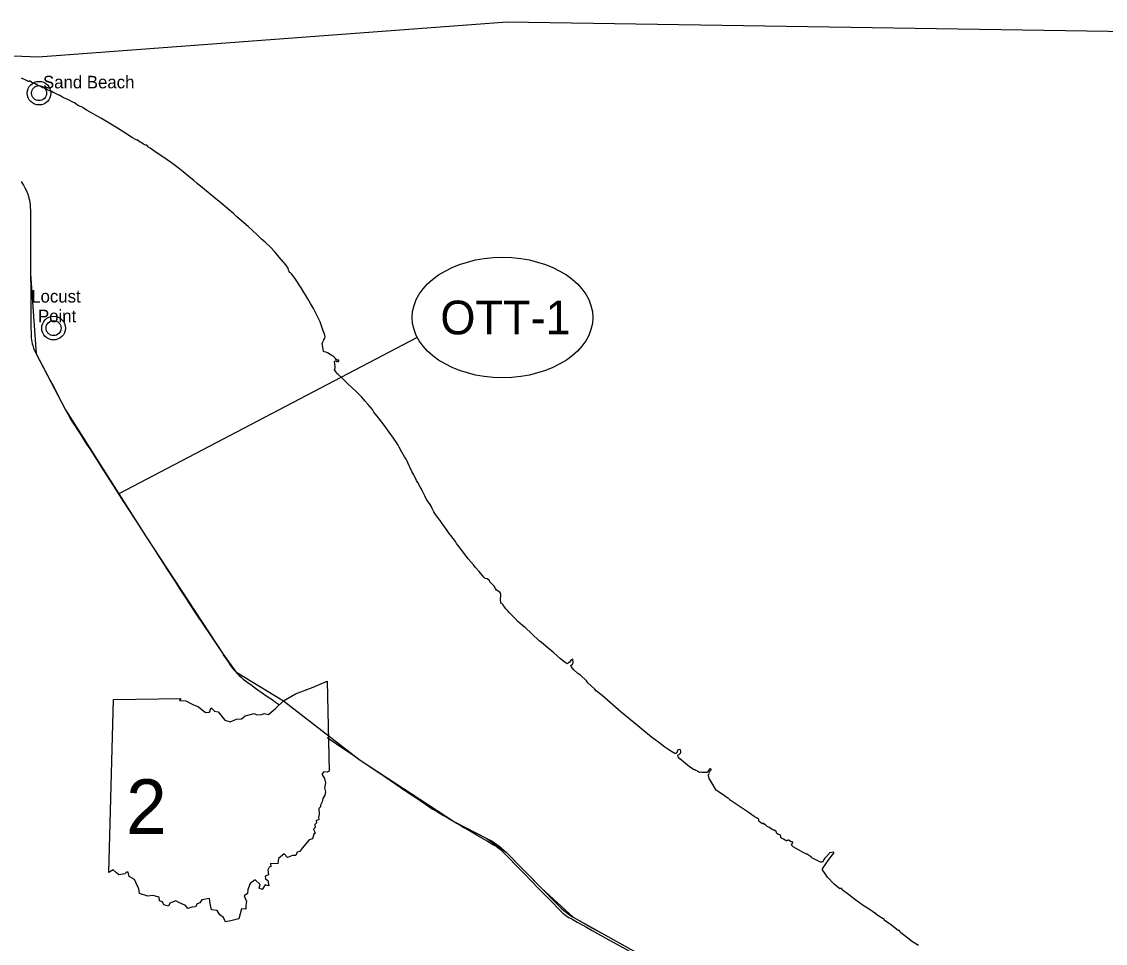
# Model space of a CAD drawing. Extents: x -82 to 873, y 0 to 440.
# Drawn here: x 310.6 to 400.6, y 192.1 to 268.6 of the extents above; entities that cross this region are included whole.
import ezdxf

# ---------------------------------------------------------------- set-up
doc = ezdxf.new("R2010")
doc.units = 0
for name, color, linetype in [('DV_X_Corp_Line', 7, 'Continuous'), ('DV_X_County_Line', 7, 'Continuous'), ('GM_P_US_Alignment', 7, 'Continuous'), ('GM_X_County', 7, 'Continuous'), ('GM_X_Interstate_Route', 7, 'Continuous'), ('PV_P_Text', 7, 'Continuous'), ('SH_Data', 7, 'Continuous')]:
    doc.layers.add(name, color=color, linetype=linetype)

msp = doc.modelspace()

# ---------------------------------------------------------------- linework, layer by layer
at = {"layer": 'DV_X_Corp_Line'}
for centre, radius in [((312.035, 262.713), 0.982), ((312.035, 262.713), 0.623), ((313.239, 243.203), 0.982), ((313.239, 243.203), 0.623)]:
    msp.add_circle(centre, radius, dxfattribs=at)
at = {"layer": 'DV_X_County_Line'}
for p, q in [((311.973, 265.73), (350.916, 268.65)), ((350.916, 268.65), (423.261, 267.513)), ((282.754, 267.019), (311.973, 265.73))]:
    msp.add_line(p, q, dxfattribs=at)
at = {"layer": 'GM_P_US_Alignment'}
msp.add_lwpolyline([(311.334, 247.708), (311.793, 241.068), (314.238, 236.419), (320.869, 225.952), (327.314, 216.112), (328.371, 214.651), (332.341, 212.251), (338.714, 207.336), (346.525, 202.192), (349.222, 200.826), (350.82, 199.691), (353.754, 196.704), (356.379, 194.294), (361.645, 191.348), (365.204, 189.06)], dxfattribs=at)
at = {"layer": 'GM_X_County'}
msp.add_lwpolyline([(385.067, 191.936), (384.564, 192.229), (384.181, 192.533), (383.818, 192.818), (383.564, 193.013), (383.533, 193.064), (383.51, 193.134), (383.482, 193.173), (383.436, 193.177), (383.393, 193.177), (382.721, 193.708), (382.254, 194.008), (382.241, 194.074), (382.226, 194.117), (382.187, 194.145), (382.132, 194.145), (381.781, 194.371), (381.57, 194.519), (381.535, 194.578), (381.496, 194.609), (381.445, 194.613), (381.238, 194.757), (381.043, 194.905), (380.477, 195.261), (379.865, 195.709), (379.256, 196.154), (378.725, 196.552), (378.702, 196.661), (378.643, 196.7), (378.542, 196.646), (378.077, 197.032), (377.515, 197.606), (377.34, 197.848), (377.086, 198.214), (377.103, 198.29), (377.375, 198.712), (377.572, 198.989), (377.825, 199.319), (378.036, 199.613), (378.04, 199.693), (377.691, 199.615), (377.638, 199.565), (377.431, 199.332), (377.281, 199.188), (377.248, 199.096), (377.084, 198.856), (376.941, 198.86), (376.495, 199.062), (376.163, 199.25), (376.174, 199.278), (375.78, 199.538), (375.755, 199.523), (375.535, 199.636), (374.656, 200.133), (374.594, 200.18), (374.547, 200.231), (374.525, 200.287), (374.585, 200.365), (374.619, 200.428), (374.644, 200.465), (374.626, 200.51), (374.578, 200.55), (374.549, 200.543), (374.515, 200.529), (374.481, 200.535), (374.286, 200.667), (374.232, 200.671), (374.204, 200.643), (374.172, 200.64), (374.126, 200.598), (373.851, 200.761), (373.648, 200.877), (373.643, 201.014), (373.617, 201.075), (373.516, 201.116), (373.435, 201.136), (373.292, 201.238), (373.287, 201.324), (373.252, 201.39), (373.171, 201.441), (373.155, 201.491), (373.135, 201.522), (373.018, 201.522), (372.917, 201.552), (372.653, 201.76), (372.511, 201.826), (372.379, 201.928), (372.257, 202.009), (372.191, 202.09), (372.115, 202.07), (372.085, 202.049), (371.811, 202.257), (371.816, 202.389), (371.679, 202.496), (371.588, 202.521), (371.42, 202.653), (370.913, 203.013), (369.517, 203.952), (369.441, 204.014), (369.345, 204.081), (369.306, 204.144), (369.239, 204.158), (368.956, 204.35), (368.442, 204.715), (368.274, 204.84), (367.914, 205.43), (367.698, 205.79), (367.626, 206.039), (367.631, 206.121), (367.684, 206.174), (367.708, 206.246), (367.698, 206.299), (367.698, 206.332), (367.713, 206.39), (367.761, 206.428), (367.809, 206.462), (367.838, 206.515), (367.842, 206.567), (367.804, 206.615), (367.742, 206.615), (367.689, 206.553), (367.617, 206.419), (367.487, 206.294), (367.391, 206.289), (367.113, 206.289), (367.012, 206.313), (366.897, 206.303), (366.81, 206.342), (366.714, 206.404), (366.566, 206.476), (366.489, 206.51), (366.431, 206.514), (366.052, 206.769), (365.707, 207.033), (365.241, 207.421), (365.121, 207.609), (365.087, 207.705), (365.121, 207.777), (365.203, 207.805), (365.303, 207.897), (365.337, 207.978), (365.337, 208.079), (365.294, 208.17), (365.217, 208.204), (365.111, 208.18), (365.054, 208.112), (365.03, 208.055), (364.996, 207.92), (364.929, 207.868), (364.847, 207.872), (364.507, 208.06), (363.998, 208.4), (363.504, 208.799), (362.904, 209.23), (362.256, 209.758), (361.766, 210.161), (360.374, 211.308), (359.712, 211.884), (358.795, 212.69), (358.339, 213.055), (358.171, 213.252), (357.619, 213.736), (357.504, 213.905), (357, 214.37), (356.77, 214.533), (356.448, 214.831), (356.223, 215.095), (356.21, 215.171), (356.323, 215.306), (356.381, 215.397), (356.371, 215.709), (356.174, 215.56), (356.088, 215.473), (355.987, 215.378), (355.882, 215.315), (355.738, 215.421), (355.339, 215.747), (354.783, 216.222), (354.159, 216.769), (353.746, 217.115), (353.583, 217.206), (352.93, 217.835), (352.416, 218.343), (352.176, 218.516), (351.807, 218.847), (351.581, 219.087), (351.087, 219.586), (350.948, 219.745), (350.799, 219.903), (350.655, 220.076), (350.578, 220.177), (350.564, 220.215), (350.453, 220.325), (350.396, 220.369), (350.367, 220.68), (350.381, 220.978), (350.376, 221.103), (350.343, 221.204), (350.29, 221.28), (350.036, 221.444), (349.954, 221.588), (349.834, 221.76), (349.58, 222.01), (349.479, 222.13), (349.441, 222.242), (349.239, 222.394), (349.085, 222.418), (348.961, 222.518), (348.586, 222.979), (348.265, 223.344), (348.116, 223.536), (347.684, 224.049), (347.295, 224.572), (346.81, 225.182), (346.705, 225.302), (346.613, 225.475), (346.239, 225.988), (346.1, 226.142), (345.97, 226.314), (345.745, 226.665), (345.524, 226.982), (345.341, 227.236), (345.217, 227.404), (345.125, 227.5), (344.914, 227.797), (344.828, 227.941), (344.689, 228.229), (344.593, 228.412), (344.501, 228.541), (344.305, 228.853), (344.156, 229.093), (344.06, 229.271), (343.954, 229.496), (343.867, 229.664), (343.724, 229.976), (343.484, 230.384), (343.383, 230.538), (343.215, 230.907), (343.172, 231.017), (342.999, 231.301), (342.836, 231.656), (342.769, 231.766), (342.682, 231.963), (342.61, 232.15), (342.523, 232.313), (342.397, 232.505), (342.167, 232.893), (341.942, 233.304), (341.871, 233.474), (341.652, 233.78), (341.334, 234.257), (341.104, 234.563), (340.704, 235.138), (340.223, 235.762), (339.845, 236.233), (339.713, 236.431), (339.522, 236.666), (339.346, 236.89), (339.089, 237.159), (338.832, 237.465), (338.7, 237.608), (338.35, 237.958), (338.059, 238.226), (337.605, 238.665), (337.145, 239.092), (336.887, 239.338), (336.772, 239.431), (336.718, 239.552), (336.574, 239.729), (336.592, 239.816), (336.626, 239.872), (336.635, 239.954), (336.592, 240.263), (336.561, 240.38), (336.574, 240.423), (336.596, 240.449), (336.657, 240.48), (336.696, 240.48), (336.731, 240.441), (336.787, 240.441), (336.835, 240.454), (336.869, 240.436), (336.915, 240.428), (336.943, 240.48), (336.939, 240.514), (336.917, 240.534), (336.878, 240.53), (336.826, 240.536), (336.778, 240.549), (336.722, 240.592), (336.644, 240.684), (336.513, 240.809), (336.353, 240.914), (336.132, 241.061), (335.984, 241.157), (335.862, 241.204), (335.737, 241.235), (335.654, 241.252), (335.541, 241.951), (335.611, 241.994), (335.637, 242.107), (335.691, 242.226), (335.762, 242.359), (335.784, 242.485), (335.767, 242.615), (335.741, 242.702), (335.624, 242.966), (335.532, 243.214), (335.367, 243.722), (335.268, 243.943), (334.959, 244.542), (334.829, 244.824), (334.59, 245.249), (334.36, 245.623), (333.792, 246.543), (333.336, 247.276), (333.206, 247.463), (333.002, 247.719), (332.923, 247.797), (332.867, 247.814), (332.802, 247.892), (332.754, 248.005), (332.715, 248.188), (332.533, 248.444), (331.986, 249.086), (331.756, 249.364), (331.587, 249.572), (331.257, 249.915), (330.862, 250.297), (330.679, 250.44), (330.51, 250.575), (330.397, 250.687), (330.111, 250.974), (329.39, 251.629), (328.461, 252.454), (328.175, 252.718), (327.71, 253.118), (327.285, 253.478), (327.124, 253.604), (326.56, 254.068), (325.77, 254.719), (325.162, 255.218), (324.889, 255.457), (324.511, 255.756), (323.995, 256.19), (323.587, 256.507), (323.153, 256.833), (322.493, 257.325), (321.838, 257.733), (321.252, 258.132), (321.074, 258.254), (321.056, 258.31), (320.922, 258.393), (320.869, 258.382), (320.712, 258.484), (320.26, 258.751), (320.271, 258.796), (320.195, 258.84), (320.149, 258.809), (319.732, 259.039), (319.377, 259.293), (318.547, 259.799), (317.208, 260.621), (316.041, 261.276), (315.724, 261.474), (315.635, 261.558), (315.459, 261.608), (315.231, 261.726), (315.082, 261.821), (314.988, 261.901), (314.884, 261.927), (314.466, 262.146), (314.083, 262.325), (313.968, 262.376), (313.853, 262.45), (313.76, 262.526), (313.736, 262.541), (313.684, 262.55), (313.499, 262.641), (313.335, 262.726), (313.289, 262.739), (313.213, 262.767), (313.083, 262.841), (312.994, 262.869), (312.9, 262.895), (312.762, 262.956), (312.673, 263.017), (312.614, 263.056), (312.534, 263.09), (312.473, 263.14), (312.351, 263.164), (312.147, 263.255), (311.954, 263.342), (311.861, 263.407), (311.867, 263.457), (311.8, 263.442), (311.644, 263.505), (311.514, 263.574), (311.427, 263.596), (311.399, 263.644), (311.34, 263.661), (311.249, 263.724), (311.21, 263.715), (311.175, 263.693), (311.132, 263.693), (311.097, 263.698), (310.871, 263.819), (310.761, 263.874), (310.676, 263.91), (310.62, 263.939), (310.572, 263.947)], dxfattribs=at)
at = {"layer": 'GM_X_Interstate_Route'}
for points in [[(310.542, 255.38), (310.634, 255.244), (310.742, 255.07), (310.859, 254.863), (310.961, 254.648), (311.014, 254.52), (311.061, 254.408), (311.147, 254.145), (311.191, 253.989), (311.227, 253.831), (311.263, 253.63), (311.29, 253.429), (311.309, 253.226), (311.318, 253.023), (311.324, 252.697), (311.321, 252.002), (311.32, 251.664), (311.318, 251.082)], [(311.318, 251.082), (311.316, 250.463), (311.318, 250.169), (311.321, 249.668), (311.334, 247.708), (311.343, 246.388), (311.348, 245.68), (311.353, 245.023), (311.354, 244.572), (311.363, 243.633), (311.363, 243.599), (311.365, 243.138), (311.367, 242.858), (311.375, 242.561), (311.384, 242.396), (311.402, 242.233), (311.427, 242.07), (311.462, 241.909), (311.506, 241.75), (311.538, 241.648), (311.58, 241.528), (311.612, 241.447), (311.627, 241.413), (311.683, 241.289), (311.793, 241.068), (312.538, 239.652), (312.643, 239.451), (312.9, 238.961), (313.112, 238.563), (313.934, 237.001), (314.238, 236.419), (314.449, 236.021), (314.608, 235.733), (314.656, 235.653), (314.755, 235.486), (315.441, 234.414), (315.984, 233.57), (316.24, 233.171), (316.771, 232.342), (317.393, 231.376), (317.935, 230.527), (318.034, 230.373), (318.197, 230.119), (319.052, 228.784), (320.449, 226.608), (320.869, 225.952), (321.609, 224.804), (321.928, 224.311), (322.513, 223.419), (322.626, 223.243), (322.846, 222.902), (323.27, 222.248), (323.785, 221.439), (324.328, 220.615), (324.415, 220.483), (324.977, 219.626), (325.84, 218.33), (326.134, 217.886), (326.791, 216.896), (327.314, 216.112)], [(327.314, 216.112), (327.337, 216.078), (327.68, 215.568), (327.936, 215.197), (328.083, 215), (328.237, 214.807), (328.371, 214.651), (328.483, 214.531), (328.653, 214.364), (328.658, 214.358), (328.81, 214.22), (328.997, 214.06), (329.19, 213.906), (329.486, 213.687), (329.609, 213.598)], [(329.609, 213.598), (330.018, 213.303), (330.674, 212.844), (331.033, 212.595), (331.299, 212.404), (331.662, 212.146), (332, 211.908)], [(335.96, 209.213), (336.137, 209.093), (336.746, 208.675), (337.187, 208.375), (338.104, 207.753), (338.714, 207.336), (340.782, 205.925), (341.664, 205.325), (342.376, 204.839), (342.79, 204.56), (343.397, 204.153), (343.968, 203.772), (344.114, 203.674), (344.444, 203.457), (344.737, 203.264), (345.124, 203.024), (345.621, 202.726), (346.001, 202.498), (346.525, 202.192), (346.713, 202.083), (347.089, 201.865), (347.37, 201.705), (347.439, 201.669)], [(347.439, 201.669), (348.192, 201.224), (348.251, 201.185), (349.282, 200.588), (349.779, 200.298), (349.99, 200.17), (350.127, 200.078), (350.258, 199.978), (350.343, 199.906), (350.384, 199.871), (350.503, 199.757), (352.198, 198.025), (353.061, 197.145), (353.357, 196.84), (353.49, 196.703), (354.009, 196.176), (354.44, 195.736), (354.67, 195.501), (355.157, 195), (355.388, 194.767), (355.536, 194.626), (355.661, 194.519), (355.757, 194.444), (355.892, 194.351), (356.03, 194.263), (356.35, 194.078), (356.709, 193.88), (357.25, 193.584), (357.501, 193.445), (357.968, 193.186), (359.116, 192.545), (362.525, 190.645)], [(347.439, 201.669), (348.622, 201.118), (349.002, 200.936), (349.222, 200.826), (349.439, 200.709), (349.651, 200.585), (349.858, 200.453), (350.061, 200.314), (350.258, 200.168), (350.403, 200.052), (350.42, 200.039), (350.451, 200.015), (350.669, 199.829), (350.82, 199.691), (351.053, 199.46), (351.915, 198.581), (352.977, 197.495), (353.381, 197.086), (353.406, 197.059), (353.754, 196.704), (355.015, 195.412), (355.218, 195.208), (355.399, 195.04), (355.616, 194.851), (355.807, 194.695), (355.971, 194.571), (356.172, 194.429), (356.379, 194.294), (356.591, 194.167), (356.983, 193.944), (357.952, 193.405), (358.776, 192.945), (361.645, 191.348)]]:
    msp.add_lwpolyline(points, dxfattribs=at)
at = {"layer": 'PV_P_Text'}
msp.add_line((317.824, 198), (318.225, 212.363), dxfattribs=at)
msp.add_line((317.824, 198), (318.225, 212.363), dxfattribs=at)
for points in [[(318.225, 212.363), (323.797, 212.457), (323.71, 212.283), (324.236, 212.247), (324.795, 211.94), (325.267, 211.746), (325.845, 211.29), (326.191, 211.295), (326.337, 211.669), (326.602, 211.38), (326.916, 211.329), (327.459, 210.641), (327.908, 210.492), (328.445, 210.728), (328.846, 210.767), (329.14, 211), (329.904, 211.199), (330.118, 211.08), (330.523, 211.104), (330.726, 211.192), (331.079, 211.113), (331.701, 211.635), (332.341, 212.251), (333.325, 212.832), (334.795, 213.383), (335.957, 213.875), (336.126, 206.422)], [(318.225, 212.363), (323.797, 212.457), (323.71, 212.283), (324.236, 212.247), (324.795, 211.94), (325.267, 211.746), (325.845, 211.29), (326.191, 211.295), (326.337, 211.669), (326.602, 211.38), (326.916, 211.329), (327.459, 210.641), (327.908, 210.492), (328.445, 210.728), (328.846, 210.767), (329.14, 211), (329.904, 211.199), (330.118, 211.08), (330.523, 211.104), (330.726, 211.192), (331.079, 211.113), (331.701, 211.635), (332.341, 212.251), (333.325, 212.832), (334.795, 213.383), (335.957, 213.875), (336.126, 206.422)], [(336.126, 206.422), (335.954, 206.317), (335.687, 206.367), (335.508, 206.157), (335.73, 205.809), (335.835, 205.44), (335.742, 205.034), (335.834, 204.699), (335.771, 204.419), (335.603, 204.14), (335.545, 203.874), (335.403, 203.593), (335.415, 203.437), (335.279, 203.312), (335.303, 202.846), (335.235, 202.588), (335.258, 202.365), (335.038, 202.306), (335.088, 202.122), (334.948, 201.98), (334.978, 201.735), (334.819, 201.579), (334.973, 201.267), (334.849, 201.167), (334.746, 200.787), (334.463, 200.71), (333.897, 200.014), (333.697, 199.751), (333.472, 199.686), (333.348, 199.416), (333.072, 199.415), (332.653, 199.228), (332.383, 199.55), (331.908, 199.162), (331.854, 198.714), (331.254, 198.728), (331.278, 198.502), (331.144, 198.436), (331.022, 198.209), (331.093, 197.806), (330.812, 197.703), (330.846, 197.469), (331.026, 197.326), (331.106, 196.879), (330.808, 196.969), (330.563, 196.592), (330.312, 196.681), (330.394, 197), (329.97, 197.384), (329.568, 197.077), (329.359, 196.585), (329.356, 196.255), (329.057, 196.055), (329.249, 195.588), (329.214, 195.266), (329.22, 194.96), (328.846, 194.971), (328.619, 194.146)], [(336.126, 206.422), (335.954, 206.317), (335.687, 206.367), (335.508, 206.157), (335.73, 205.809), (335.835, 205.44), (335.742, 205.034), (335.834, 204.699), (335.771, 204.419), (335.603, 204.14), (335.545, 203.874), (335.403, 203.593), (335.415, 203.437), (335.279, 203.312), (335.303, 202.846), (335.235, 202.588), (335.258, 202.365), (335.038, 202.306), (335.088, 202.122), (334.948, 201.98), (334.978, 201.735), (334.819, 201.579), (334.973, 201.267), (334.849, 201.167), (334.746, 200.787), (334.463, 200.71), (333.897, 200.014), (333.697, 199.751), (333.472, 199.686), (333.348, 199.416), (333.072, 199.415), (332.653, 199.228), (332.383, 199.55), (331.908, 199.162), (331.854, 198.714), (331.254, 198.728), (331.278, 198.502), (331.144, 198.436), (331.022, 198.209), (331.093, 197.806), (330.812, 197.703), (330.846, 197.469), (331.026, 197.326), (331.106, 196.879), (330.808, 196.969), (330.563, 196.592), (330.312, 196.681), (330.394, 197), (329.97, 197.384), (329.568, 197.077), (329.359, 196.585), (329.356, 196.255), (329.057, 196.055), (329.249, 195.588), (329.214, 195.266), (329.22, 194.96), (328.846, 194.971), (328.619, 194.146)], [(328.619, 194.146), (327.969, 193.989), (327.518, 193.894), (327.358, 194.269), (327.036, 194.466), (326.825, 194.844), (326.362, 194.895), (326.252, 195.413), (326.2, 195.833), (325.566, 195.729), (325.392, 195.472), (325.168, 195.403), (325.037, 195.144), (324.731, 195.123), (324.402, 195.001), (324.187, 195.254), (323.648, 195.509), (323.406, 195.641), (322.899, 195.436), (322.791, 195.195), (322.388, 195.301), (322.294, 195.571), (322.05, 195.652), (321.996, 195.938), (321.474, 196.09), (321.075, 196.03), (320.372, 196.26), (320.329, 196.636), (320.09, 197.095), (319.964, 197.413), (319.52, 197.656), (319.43, 198.035), (319.287, 198.024), (319.157, 197.87), (318.663, 197.799), (318.466, 197.954), (318.189, 198.218), (317.824, 198)], [(328.619, 194.146), (327.969, 193.989), (327.518, 193.894), (327.358, 194.269), (327.036, 194.466), (326.825, 194.844), (326.362, 194.895), (326.252, 195.413), (326.2, 195.833), (325.566, 195.729), (325.392, 195.472), (325.168, 195.403), (325.037, 195.144), (324.731, 195.123), (324.402, 195.001), (324.187, 195.254), (323.648, 195.509), (323.406, 195.641), (322.899, 195.436), (322.791, 195.195), (322.388, 195.301), (322.294, 195.571), (322.05, 195.652), (321.996, 195.938), (321.474, 196.09), (321.075, 196.03), (320.372, 196.26), (320.329, 196.636), (320.09, 197.095), (319.964, 197.413), (319.52, 197.656), (319.43, 198.035), (319.287, 198.024), (319.157, 197.87), (318.663, 197.799), (318.466, 197.954), (318.189, 198.218), (317.824, 198)]]:
    msp.add_lwpolyline(points, dxfattribs=at)
at = {"layer": 'SH_Data'}
msp.add_line((343.442, 242.433), (318.659, 229.439), dxfattribs=at)
msp.add_ellipse((350.522, 244.083), major_axis=(7.5, 0), ratio=0.666667, dxfattribs=at)

# ---------------------------------------------------------------- texts
at = {"layer": 'DV_X_Corp_Line'}
for s, p in [('Sand Beach', (312.363, 263.111)), ('Locust', (311.385, 245.324)), ('Point', (311.946, 243.685))]:
    msp.add_text(s, height=1.0417, rotation=0.00501, dxfattribs=at).set_placement(p)
at = {"layer": 'PV_P_Text'}
msp.add_text(' 2 ', height=4.5281, rotation=0.005, dxfattribs=at).set_placement((317.586, 201.203))
at = {"layer": 'SH_Data'}
msp.add_text('OTT-1', height=2.8, dxfattribs=at).set_placement((345.362, 242.683))

doc.saveas('drawing.dxf')
